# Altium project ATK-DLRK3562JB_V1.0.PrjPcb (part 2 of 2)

## Sheet 11_ATK-DLRK3562JB_RGMII_NET.SchDoc
size A4; Author: ALIENTEK; Revision: 0; SheetNumber: 11; SheetTotal: 11; Version: V1.0; SheetSize: A4
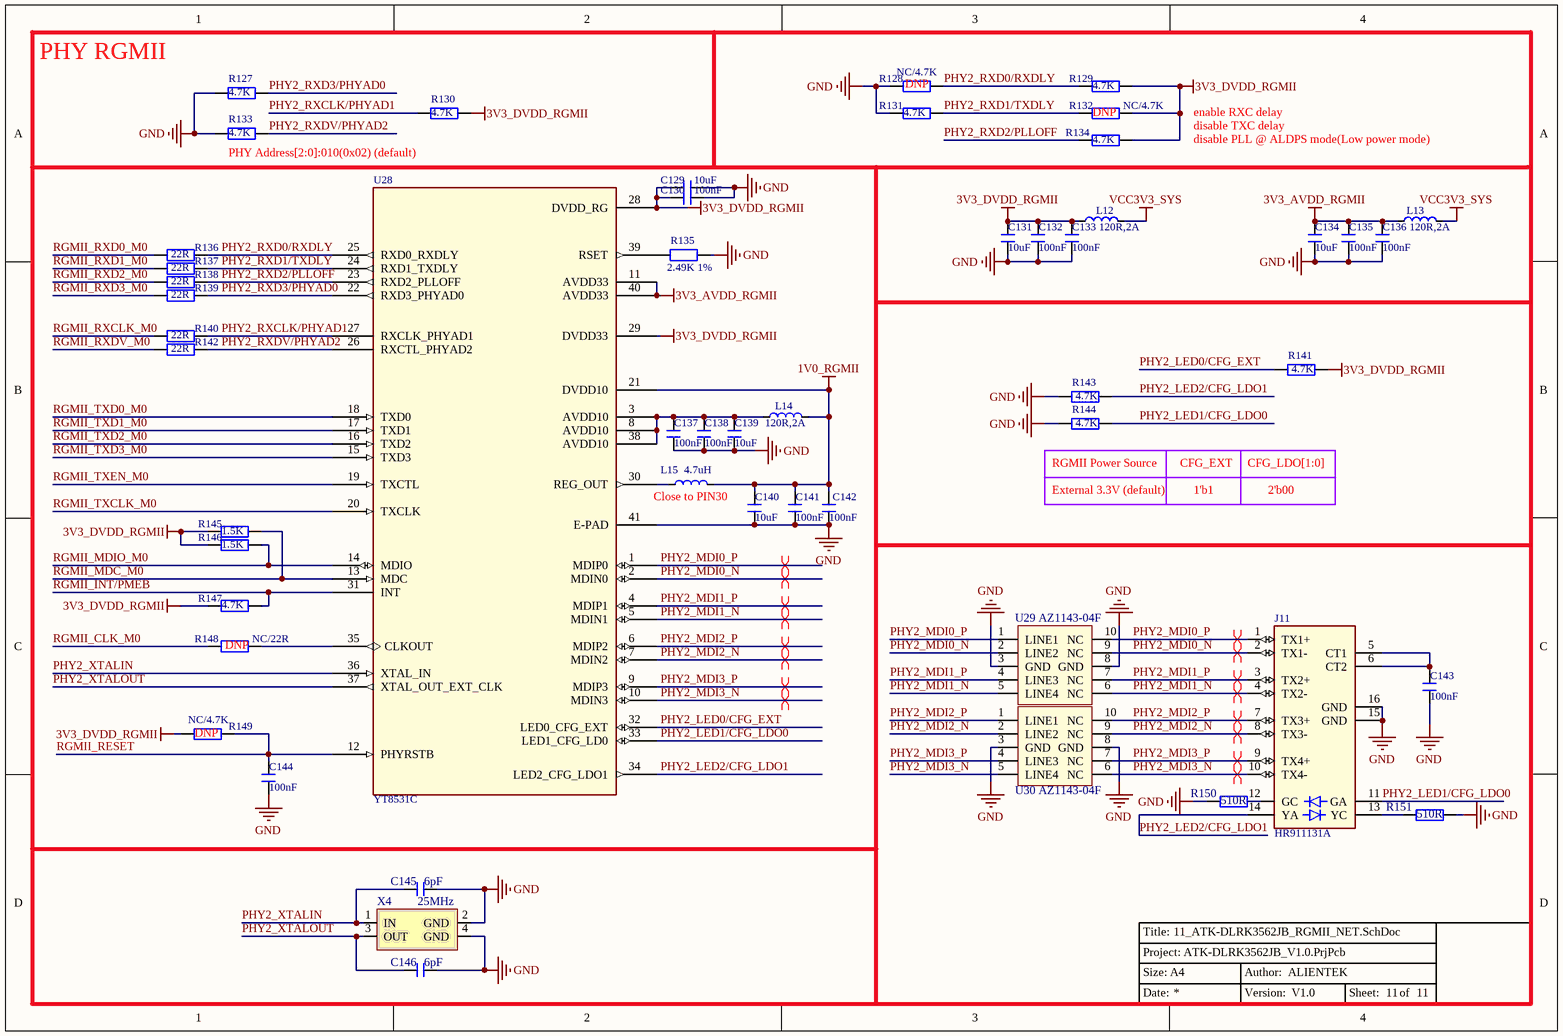
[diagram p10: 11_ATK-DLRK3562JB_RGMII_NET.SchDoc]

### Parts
C129  10uF  [C 0805]
C130  100nF  [C 0402]
C131  10uF  [C 0805]
C132  100nF  [C 0402]
C133  100nF  [C 0402]
C134  10uF  [C 0805]
C135  100nF  [C 0402]
C136  100nF  [C 0402]
C137  100nF  [C 0402]
C138  100nF  [C 0402]
C139  10uF  [C 0805]
C140  10uF  [C 0805]
C141  100nF  [C 0402]
C142  100nF  [C 0402]
C143  100nF  [C 0402]
C144  100nF  [C 0402]
C145  6pF  [C 0402]
C146  6pF  [C 0402]
J11  HR911131A  [HR911131A]
L12  120R,2A  [L 0603]
L13  120R,2A  [L 0603]
L14  120R,2A  [L 0603]
L15  4.7uH  [L_2520]
R127  4.7K  [R 0402]
R128  NC/4.7K  [R 0402]
R129  4.7K  [R 0402]
R130  4.7K  [R 0402]
R131  4.7K  [R 0402]
R132  NC/4.7K  [R 0402]
R133  4.7K  [R 0402]
R134  4.7K  [R 0402]
R135  2.49K 1%  [R 0402]
R136  22R  [R 0402]
R137  22R  [R 0402]
R138  22R  [R 0402]
R139  22R  [R 0402]
R140  22R  [R 0402]
R141  4.7K  [R 0402]
R142  22R  [R 0402]
R143  4.7K  [R 0402]
R144  4.7K  [R 0402]
R145  1.5K  [R 0402]
R146  1.5K  [R 0402]
R147  4.7K  [R 0402]
R148  NC/22R  [R 0402]
R149  NC/4.7K  [R 0402]
R150  510R  [R 0402]
R151  510R  [R 0402]
U28  YT8531C  [QFN40]
U29  AZ1143-04F  [DFN2510P10E]
U30  AZ1143-04F  [DFN2510P10E]
X4  25MHz  [XTAL-3225]

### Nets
1V0_RGMII: C140.2 C141.2 C142.2 L14.2 L15.2 U28.21(DVDD10)
3V3_AVDD_RGMII: C134.2 C135.2 C136.2 L13.1 U28.11(AVDD33) U28.40(AVDD33)
3V3_DVDD_RGMII: C129.2 C130.2 C131.2 C132.2 C133.2 L12.1 R129.2 R130.2 R132.2 R134.2 R141.2 R145.1 R146.1 R147.1 R149.2 U28.28(DVDD_RG) U28.29(DVDD33)
GND: C129.1 C130.1 C131.1 C132.1 C133.1 C134.1 C135.1 C136.1 C137.1 C138.1 C139.1 C140.1 C141.1 C142.1 C143.1 C144.1 C145.2 C146.2 J11.15(GND) J11.16(GND) R127.2 R128.1 R131.1 R133.2 R135.2 R143.1 R144.1 R150.1 R151.2 U28.41(E-PAD) U29.3(GND) U29.8(GND) U30.3(GND) U30.8(GND) X4.2(GND) X4.4(GND)
VCC3V3_SYS: L12.2 L13.2
PHY2_LED0/CFG_EXT: R141.1 U28.32(LED0_CFG_EXT)
PHY2_LED1/CFG_LDO0: J11.11(GA) R144.2 U28.33(LED1_CFG_LD0)
PHY2_LED2/CFG_LDO1: J11.14(YA) R143.2 U28.34(LED2_CFG_LDO1)
PHY2_MDI0_N: J11.2(TX1-) U28.2(MDIN0) U29.2(LINE2) U29.9(NC)
PHY2_MDI0_P: J11.1(TX1+) U28.1(MDIP0) U29.1(LINE1) U29.10(NC)
PHY2_MDI1_N: J11.4(TX2-) U28.5(MDIN1) U29.5(LINE4) U29.6(NC)
PHY2_MDI1_P: J11.3(TX2+) U28.4(MDIP1) U29.4(LINE3) U29.7(NC)
PHY2_MDI2_N: J11.8(TX3-) U28.7(MDIN2) U30.2(LINE2) U30.9(NC)
PHY2_MDI2_P: J11.7(TX3+) U28.6(MDIP2) U30.1(LINE1) U30.10(NC)
PHY2_MDI3_N: J11.10(TX4-) U28.10(MDIN3) U30.5(LINE4) U30.6(NC)
PHY2_MDI3_P: J11.9(TX4+) U28.9(MDIP3) U30.4(LINE3) U30.7(NC)
PHY2_RXCLK/PHYAD1: R130.1 R140.1 U28.27(RXCLK_PHYAD1)
PHY2_RXD0/RXDLY: R128.2 R129.1 R136.1 U28.25(RXD0_RXDLY)
PHY2_RXD1/TXDLY: R131.2 R132.1 R137.1 U28.24(RXD1_TXDLY)
PHY2_RXD2/PLLOFF: R134.1 R138.1 U28.23(RXD2_PLLOFF)
PHY2_RXD3/PHYAD0: R127.1 R139.1 U28.22(RXD3_PHYAD0)
PHY2_RXDV/PHYAD2: R133.1 R142.1 U28.26(RXCTL_PHYAD2)
PHY2_XTALIN: C145.1 U28.36(XTAL_IN) X4.1(IN)
PHY2_XTALOUT: C146.1 U28.37(XTAL_OUT_EXT_CLK) X4.3(OUT)
RGMII_CLK_M0: R148.1  [project net GPIO4_B7]
RGMII_INT/PMEB: R147.2 U28.31(INT)  [project net GPIO4_B1]
RGMII_MDC_M0: R145.2 U28.13(MDC)  [project net GPIO4_B2]
RGMII_MDIO_M0: R146.2 U28.14(MDIO)  [project net GPIO4_B3]
RGMII_RESET: C144.2 R149.1 U28.12(PHYRSTB)  [project net GPIO4_B0]
RGMII_RXCLK_M0: R140.2  [project net GPIO4_A1]
RGMII_RXD0_M0: R136.2  [project net GPIO4_A5]
RGMII_RXD1_M0: R137.2  [project net GPIO4_A6]
RGMII_RXD2_M0: R138.2  [project net GPIO3_D7]
RGMII_RXD3_M0: R139.2  [project net GPIO4_A0]
RGMII_RXDV_M0: R142.2  [project net GPIO4_A7]
RGMII_TXCLK_M0: U28.20(TXCLK)  [project net GPIO3_D6]
RGMII_TXD0_M0: U28.18(TXD0)  [project net GPIO4_A2]
RGMII_TXD1_M0: U28.17(TXD1)  [project net GPIO4_A3]
RGMII_TXD2_M0: U28.16(TXD2)  [project net GPIO3_D4]
RGMII_TXD3_M0: U28.15(TXD3)  [project net GPIO3_D5]
RGMII_TXEN_M0: U28.19(TXCTL)  [project net GPIO4_A4]
NetC137_2: C137.2 C138.2 C139.2 L14.1 U28.3(AVDD10) U28.8(AVDD10) U28.38(AVDD10)
NetC143_2: C143.2 J11.5(CT1) J11.6(CT2)
NetJ11_12: J11.12(GC) R150.2
NetJ11_13: J11.13(YC) R151.1
NetL15_1: L15.1 U28.30(REG_OUT)
NetR135_1: R135.1 U28.39(RSET)
NetR148_2: R148.2 U28.35(CLKOUT)

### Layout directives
differential pair: PHY2_MDI0_N, PHY2_MDI0_P, PHY2_MDI1_N, PHY2_MDI1_P, PHY2_MDI2_N, PHY2_MDI2_P, PHY2_MDI3_N, PHY2_MDI3_P

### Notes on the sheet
- PHY RGMII
- (near R128) DNP
- (near R132) DNP
- enable RXC delay
- (near R133) PHY Address[2:0]:010(0x02) (default)
- disable PLL @ ALDPS mode(Low power mode)
- disable TXC delay
- (near L15) Close to PIN30
- (near R144) RGMII Power Source
- External 3.3V (default)
- CFG_EXT
- 1'b1
- CFG_LDO[1:0]
- 2'b00
- (near R148) DNP
- (near R149) DNP

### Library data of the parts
C129-C144 = C: 无极性贴片电容; 版权归属: 源创客
C145 C146 = C: 无极性电容; BOM名称: 无极性贴片电容; 版权归属: 正点原子
J11 = HR911131A/C: 千兆以太网接口
L12-L15 = L: 小功率贴片电感磁珠; 版权归属: 源创客
R127-R149 = R: 贴片电阻; 版权归属: 源创客
R150 R151 = R: 贴片电阻; 版权归属: 正点原子
U28 = YT8531C: 千兆以太网
U29 U30 = AZ1143-04F: ESD保护二极管阵列
X4 = XTAL-4P: 4脚无源晶振; BOM名称: 4脚晶振; 版权归属: 正点原子; Parameter: 晶振

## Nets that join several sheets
GND: 02_ATK-DLRK3562JB_CORE_BOARD (72 pins), 03_ATK-DLRK3562JB_POWER_UART (52 pins), 04_ATK-DLRK3562JB_DEVICE1 (19 pins), 05_ATK-DLRK3562JB_DEVICE2 (45 pins), 06_ATK-DLRK3562JB_4G_HUB (40 pins), 07_ATK-DLRK3562JB_WIFI_TF_OTG_PINOUT (55 pins), 08_ATK-DLRK3562JB_PCIE_AUDIO (31 pins), 09_ATK-DLRK3562JB_LCD_CAMERA (45 pins), 10_ATK-DLRK3562JB_RMII_NET (24 pins), 11_ATK-DLRK3562JB_RGMII_NET (36 pins)
VCC3V3_SD: 02_ATK-DLRK3562JB_CORE_BOARD (U1.A9), 07_ATK-DLRK3562JB_WIFI_TF_OTG_PINOUT (L7.2)
VCC3V3_SYS: 02_ATK-DLRK3562JB_CORE_BOARD (8 pins), 03_ATK-DLRK3562JB_POWER_UART (11 pins), 04_ATK-DLRK3562JB_DEVICE1 (MOS2.1 R27.2), 05_ATK-DLRK3562JB_DEVICE2 (31 pins), 06_ATK-DLRK3562JB_4G_HUB (C97.2 L6.2), 07_ATK-DLRK3562JB_WIFI_TF_OTG_PINOUT (9 pins), 09_ATK-DLRK3562JB_LCD_CAMERA (8 pins), 10_ATK-DLRK3562JB_RMII_NET (L10.1 L11.1), 11_ATK-DLRK3562JB_RGMII_NET (L12.2 L13.2)
VCC5V0_SYS: 02_ATK-DLRK3562JB_CORE_BOARD (8 pins), 03_ATK-DLRK3562JB_POWER_UART (9 pins), 04_ATK-DLRK3562JB_DEVICE1 (R28.2), 05_ATK-DLRK3562JB_DEVICE2 (C46.1 C47.1 U13.3 U14.3), 07_ATK-DLRK3562JB_WIFI_TF_OTG_PINOUT (J9.2 J9.4), 08_ATK-DLRK3562JB_PCIE_AUDIO (C58.2 C59.2 R58.1 U16.1), 09_ATK-DLRK3562JB_LCD_CAMERA (7 pins)
VCC5V0_USB: 03_ATK-DLRK3562JB_POWER_UART (6 pins), 06_ATK-DLRK3562JB_4G_HUB (L5.2 U20.5 USB_HOST1.1 USB_HOST2.1), 07_ATK-DLRK3562JB_WIFI_TF_OTG_PINOUT (L9.1)
VCC12V_DCIN: 03_ATK-DLRK3562JB_POWER_UART (16 pins), 04_ATK-DLRK3562JB_DEVICE1 (C31.1 C32.1 J4.2), 08_ATK-DLRK3562JB_PCIE_AUDIO (7 pins)
VCC_1V8: 02_ATK-DLRK3562JB_CORE_BOARD (U1.A111), 04_ATK-DLRK3562JB_DEVICE1 (R30.1 R31.1 VR.3), 09_ATK-DLRK3562JB_LCD_CAMERA (13 pins)
VCCIO_SD: 02_ATK-DLRK3562JB_CORE_BOARD (U1.A112), 07_ATK-DLRK3562JB_WIFI_TF_OTG_PINOUT (R96.1 R100.1)
CAM0_PWDN: 02_ATK-DLRK3562JB_CORE_BOARD (U1.B57), 07_ATK-DLRK3562JB_WIFI_TF_OTG_PINOUT (J9.13), 09_ATK-DLRK3562JB_LCD_CAMERA (R63.1)
CAM0_RESET: 02_ATK-DLRK3562JB_CORE_BOARD (U1.B58), 07_ATK-DLRK3562JB_WIFI_TF_OTG_PINOUT (J9.15), 09_ATK-DLRK3562JB_LCD_CAMERA (R62.1)
CAM1_PWDN: 02_ATK-DLRK3562JB_CORE_BOARD (U1.B56), 07_ATK-DLRK3562JB_WIFI_TF_OTG_PINOUT (J9.11), 09_ATK-DLRK3562JB_LCD_CAMERA (R78.1)
CAM1_RESET: 02_ATK-DLRK3562JB_CORE_BOARD (U1.B59), 07_ATK-DLRK3562JB_WIFI_TF_OTG_PINOUT (J9.19), 09_ATK-DLRK3562JB_LCD_CAMERA (R73.1)
CAN0_RX: 02_ATK-DLRK3562JB_CORE_BOARD (U1.A86), 05_ATK-DLRK3562JB_DEVICE2 (U13.4)
CAN0_TX: 02_ATK-DLRK3562JB_CORE_BOARD (U1.A85), 05_ATK-DLRK3562JB_DEVICE2 (U13.1)
CAN1_RX: 02_ATK-DLRK3562JB_CORE_BOARD (U1.A84), 05_ATK-DLRK3562JB_DEVICE2 (U14.4)
CAN1_TX: 02_ATK-DLRK3562JB_CORE_BOARD (U1.A83), 05_ATK-DLRK3562JB_DEVICE2 (U14.1)
DSI_RESET: 02_ATK-DLRK3562JB_CORE_BOARD (U1.B81), 07_ATK-DLRK3562JB_WIFI_TF_OTG_PINOUT (J9.7), 09_ATK-DLRK3562JB_LCD_CAMERA (R70.1)
GPIO0_A0: 02_ATK-DLRK3562JB_CORE_BOARD (U1.A54), 07_ATK-DLRK3562JB_WIFI_TF_OTG_PINOUT (J9.3), 09_ATK-DLRK3562JB_LCD_CAMERA (LVDS.28 MIPI_DSI.21)
GPIO0_A4: 02_ATK-DLRK3562JB_CORE_BOARD (U1.A68), 07_ATK-DLRK3562JB_WIFI_TF_OTG_PINOUT (R103.2)
GPIO0_A5: 02_ATK-DLRK3562JB_CORE_BOARD (U1.A92), 08_ATK-DLRK3562JB_PCIE_AUDIO (J8.B17 R110.2)
GPIO0_A6: 02_ATK-DLRK3562JB_CORE_BOARD (U1.A91), 08_ATK-DLRK3562JB_PCIE_AUDIO (J8.B12)
GPIO0_B0: 02_ATK-DLRK3562JB_CORE_BOARD (U1.A55), 07_ATK-DLRK3562JB_WIFI_TF_OTG_PINOUT (J9.5), 09_ATK-DLRK3562JB_LCD_CAMERA (LVDS.36 MIPI_DSI.24)
GPIO0_B1: 02_ATK-DLRK3562JB_CORE_BOARD (U1.A102), 07_ATK-DLRK3562JB_WIFI_TF_OTG_PINOUT (J9.10)
GPIO0_B2: 02_ATK-DLRK3562JB_CORE_BOARD (U1.A101), 07_ATK-DLRK3562JB_WIFI_TF_OTG_PINOUT (J9.12)
GPIO0_B3: 02_ATK-DLRK3562JB_CORE_BOARD (U1.A100), 05_ATK-DLRK3562JB_DEVICE2 (R35.1 U8.6 U9.6), 07_ATK-DLRK3562JB_WIFI_TF_OTG_PINOUT (J9.16 U25.6)
GPIO0_B4: 02_ATK-DLRK3562JB_CORE_BOARD (U1.A99), 05_ATK-DLRK3562JB_DEVICE2 (R36.1 U8.5 U9.5), 07_ATK-DLRK3562JB_WIFI_TF_OTG_PINOUT (J9.18 U25.7)
GPIO0_B5: 02_ATK-DLRK3562JB_CORE_BOARD (U1.A90), 08_ATK-DLRK3562JB_PCIE_AUDIO (J8.A11)
GPIO0_B6: 02_ATK-DLRK3562JB_CORE_BOARD (U1.A89), 08_ATK-DLRK3562JB_PCIE_AUDIO (J8.B11 R34.2)
GPIO0_B7: 02_ATK-DLRK3562JB_CORE_BOARD (U1.A88), 08_ATK-DLRK3562JB_PCIE_AUDIO (R83.1 R88.2)
GPIO0_C2: 02_ATK-DLRK3562JB_CORE_BOARD (U1.A95), 05_ATK-DLRK3562JB_DEVICE2 (U10.1), 07_ATK-DLRK3562JB_WIFI_TF_OTG_PINOUT (J9.26)
GPIO0_C3: 02_ATK-DLRK3562JB_CORE_BOARD (U1.A94), 05_ATK-DLRK3562JB_DEVICE2 (U10.6), 07_ATK-DLRK3562JB_WIFI_TF_OTG_PINOUT (J9.22)
GPIO0_C4: 02_ATK-DLRK3562JB_CORE_BOARD (U1.A96), 05_ATK-DLRK3562JB_DEVICE2 (U10.5), 07_ATK-DLRK3562JB_WIFI_TF_OTG_PINOUT (J9.24)
GPIO0_C5: 02_ATK-DLRK3562JB_CORE_BOARD (U1.A97), 05_ATK-DLRK3562JB_DEVICE2 (U10.2), 07_ATK-DLRK3562JB_WIFI_TF_OTG_PINOUT (J9.28)
GPIO0_D0: 02_ATK-DLRK3562JB_CORE_BOARD (U1.A53), 03_ATK-DLRK3562JB_POWER_UART (J3.3)
GPIO0_D1: 02_ATK-DLRK3562JB_CORE_BOARD (U1.A52), 03_ATK-DLRK3562JB_POWER_UART (J3.1)
GPIO1_B3: 02_ATK-DLRK3562JB_CORE_BOARD (U1.A70), 07_ATK-DLRK3562JB_WIFI_TF_OTG_PINOUT (R100.2 R101.2)
GPIO1_B4: 02_ATK-DLRK3562JB_CORE_BOARD (U1.A69), 07_ATK-DLRK3562JB_WIFI_TF_OTG_PINOUT (R102.2)
GPIO1_B5: 02_ATK-DLRK3562JB_CORE_BOARD (U1.A74), 07_ATK-DLRK3562JB_WIFI_TF_OTG_PINOUT (R95.2)
GPIO1_B6: 02_ATK-DLRK3562JB_CORE_BOARD (U1.A73), 07_ATK-DLRK3562JB_WIFI_TF_OTG_PINOUT (R97.2)
GPIO1_B7: 02_ATK-DLRK3562JB_CORE_BOARD (U1.A72), 07_ATK-DLRK3562JB_WIFI_TF_OTG_PINOUT (R96.2 R98.2)
GPIO1_C0: 02_ATK-DLRK3562JB_CORE_BOARD (U1.A71), 07_ATK-DLRK3562JB_WIFI_TF_OTG_PINOUT (R99.2)
GPIO1_C1: 02_ATK-DLRK3562JB_CORE_BOARD (U1.A77), 07_ATK-DLRK3562JB_WIFI_TF_OTG_PINOUT (J9.35)
GPIO1_C2: 02_ATK-DLRK3562JB_CORE_BOARD (U1.A78), 07_ATK-DLRK3562JB_WIFI_TF_OTG_PINOUT (J9.33)
GPIO1_C3: 02_ATK-DLRK3562JB_CORE_BOARD (U1.A76), 07_ATK-DLRK3562JB_WIFI_TF_OTG_PINOUT (J9.37)
GPIO1_C4: 02_ATK-DLRK3562JB_CORE_BOARD (U1.A79), 07_ATK-DLRK3562JB_WIFI_TF_OTG_PINOUT (J9.31)
GPIO1_C5: 02_ATK-DLRK3562JB_CORE_BOARD (U1.A80), 07_ATK-DLRK3562JB_WIFI_TF_OTG_PINOUT (J9.29)
GPIO1_C6: 02_ATK-DLRK3562JB_CORE_BOARD (U1.A81), 07_ATK-DLRK3562JB_WIFI_TF_OTG_PINOUT (J9.27)
GPIO1_C7: 02_ATK-DLRK3562JB_CORE_BOARD (U1.A49), 10_ATK-DLRK3562JB_RMII_NET (R120.2 U26.22)
GPIO1_D0: 02_ATK-DLRK3562JB_CORE_BOARD (U1.A50), 10_ATK-DLRK3562JB_RMII_NET (R119.2 U26.23)
GPIO1_D1: 02_ATK-DLRK3562JB_CORE_BOARD (U1.A40), 10_ATK-DLRK3562JB_RMII_NET (U26.16)
GPIO1_D2: 02_ATK-DLRK3562JB_CORE_BOARD (U1.A41), 10_ATK-DLRK3562JB_RMII_NET (U26.17)
GPIO1_D3: 02_ATK-DLRK3562JB_CORE_BOARD (U1.A42), 10_ATK-DLRK3562JB_RMII_NET (U26.20)
GPIO1_D4: 02_ATK-DLRK3562JB_CORE_BOARD (U1.A43), 10_ATK-DLRK3562JB_RMII_NET (U26.9)
GPIO1_D5: 02_ATK-DLRK3562JB_CORE_BOARD (U1.A47), 10_ATK-DLRK3562JB_RMII_NET (R118.1)
GPIO1_D6: 02_ATK-DLRK3562JB_CORE_BOARD (U1.A46), 10_ATK-DLRK3562JB_RMII_NET (U26.26)
GPIO1_D7: 02_ATK-DLRK3562JB_CORE_BOARD (U1.A44), 10_ATK-DLRK3562JB_RMII_NET (R109.2 U26.10)
GPIO2_A0: 02_ATK-DLRK3562JB_CORE_BOARD (U1.A45), 10_ATK-DLRK3562JB_RMII_NET (U26.28)
GPIO2_A1: 02_ATK-DLRK3562JB_CORE_BOARD (U1.A48), 10_ATK-DLRK3562JB_RMII_NET (C122.2 R123.2 U26.21)
GPIO3_A0: 02_ATK-DLRK3562JB_CORE_BOARD (U1.B80), 07_ATK-DLRK3562JB_WIFI_TF_OTG_PINOUT (R106.2 U24.4)
GPIO3_A1: 02_ATK-DLRK3562JB_CORE_BOARD (U1.B79), 07_ATK-DLRK3562JB_WIFI_TF_OTG_PINOUT (R18.2 U25.5)
GPIO3_A7: 02_ATK-DLRK3562JB_CORE_BOARD (U1.B112), 07_ATK-DLRK3562JB_WIFI_TF_OTG_PINOUT (J9.8), 08_ATK-DLRK3562JB_PCIE_AUDIO (R54.1 R55.2)
GPIO3_B2: 02_ATK-DLRK3562JB_CORE_BOARD (U1.B72), 05_ATK-DLRK3562JB_DEVICE2 (R114.1 U12.4)
GPIO3_B3: 02_ATK-DLRK3562JB_CORE_BOARD (U1.B71), 05_ATK-DLRK3562JB_DEVICE2 (R46.1 U12.1)
GPIO3_B6: 02_ATK-DLRK3562JB_CORE_BOARD (U1.B51), 09_ATK-DLRK3562JB_LCD_CAMERA (Q5.3 R66.1)
GPIO3_B7: 02_ATK-DLRK3562JB_CORE_BOARD (U1.B52), 09_ATK-DLRK3562JB_LCD_CAMERA (Q6.3 R68.1)
GPIO3_C2: 02_ATK-DLRK3562JB_CORE_BOARD (U1.B53), 09_ATK-DLRK3562JB_LCD_CAMERA (Q7.3 R74.1)
GPIO3_C3: 02_ATK-DLRK3562JB_CORE_BOARD (U1.B54), 09_ATK-DLRK3562JB_LCD_CAMERA (Q8.3 R79.1)
GPIO3_C4: 02_ATK-DLRK3562JB_CORE_BOARD (U1.B74), 05_ATK-DLRK3562JB_DEVICE2 (R111.1 U11.4)
GPIO3_C5: 02_ATK-DLRK3562JB_CORE_BOARD (U1.B47), 07_ATK-DLRK3562JB_WIFI_TF_OTG_PINOUT (J9.23), 09_ATK-DLRK3562JB_LCD_CAMERA (LVDS.27 MIPI_DSI.20)
GPIO3_C6: 02_ATK-DLRK3562JB_CORE_BOARD (U1.B45), 04_ATK-DLRK3562JB_DEVICE1 (MOS2.2 R25.1 R27.1), 07_ATK-DLRK3562JB_WIFI_TF_OTG_PINOUT (J9.21)
GPIO3_C7: 02_ATK-DLRK3562JB_CORE_BOARD (U1.B73), 05_ATK-DLRK3562JB_DEVICE2 (R45.1 U11.1)
GPIO3_D0: 02_ATK-DLRK3562JB_CORE_BOARD (U1.B76), 05_ATK-DLRK3562JB_DEVICE2 (U15.11)
GPIO3_D1: 02_ATK-DLRK3562JB_CORE_BOARD (U1.B75), 05_ATK-DLRK3562JB_DEVICE2 (U15.12)
GPIO3_D2: 02_ATK-DLRK3562JB_CORE_BOARD (U1.B49), 05_ATK-DLRK3562JB_DEVICE2 (R82.1), 09_ATK-DLRK3562JB_LCD_CAMERA (LVDS.34 MIPI_DSI.23)
GPIO3_D3: 02_ATK-DLRK3562JB_CORE_BOARD (U1.B50), 05_ATK-DLRK3562JB_DEVICE2 (R152.1), 09_ATK-DLRK3562JB_LCD_CAMERA (LVDS.33 MIPI_DSI.22)
GPIO3_D4: 02_ATK-DLRK3562JB_CORE_BOARD (U1.B93), 11_ATK-DLRK3562JB_RGMII_NET (U28.16)
GPIO3_D5: 02_ATK-DLRK3562JB_CORE_BOARD (U1.B92), 11_ATK-DLRK3562JB_RGMII_NET (U28.15)
GPIO3_D6: 02_ATK-DLRK3562JB_CORE_BOARD (U1.B90), 11_ATK-DLRK3562JB_RGMII_NET (U28.20)
GPIO3_D7: 02_ATK-DLRK3562JB_CORE_BOARD (U1.B86), 11_ATK-DLRK3562JB_RGMII_NET (R138.2)
GPIO4_A0: 02_ATK-DLRK3562JB_CORE_BOARD (U1.B85), 11_ATK-DLRK3562JB_RGMII_NET (R139.2)
GPIO4_A1: 02_ATK-DLRK3562JB_CORE_BOARD (U1.B83), 11_ATK-DLRK3562JB_RGMII_NET (R140.2)
GPIO4_A2: 02_ATK-DLRK3562JB_CORE_BOARD (U1.B95), 11_ATK-DLRK3562JB_RGMII_NET (U28.18)
GPIO4_A3: 02_ATK-DLRK3562JB_CORE_BOARD (U1.B94), 11_ATK-DLRK3562JB_RGMII_NET (U28.17)
GPIO4_A4: 02_ATK-DLRK3562JB_CORE_BOARD (U1.B91), 11_ATK-DLRK3562JB_RGMII_NET (U28.19)
GPIO4_A5: 02_ATK-DLRK3562JB_CORE_BOARD (U1.B88), 11_ATK-DLRK3562JB_RGMII_NET (R136.2)
GPIO4_A6: 02_ATK-DLRK3562JB_CORE_BOARD (U1.B87), 11_ATK-DLRK3562JB_RGMII_NET (R137.2)
GPIO4_A7: 02_ATK-DLRK3562JB_CORE_BOARD (U1.B84), 11_ATK-DLRK3562JB_RGMII_NET (R142.2)
GPIO4_B0: 02_ATK-DLRK3562JB_CORE_BOARD (U1.B40), 11_ATK-DLRK3562JB_RGMII_NET (C144.2 R149.1 U28.12)
GPIO4_B1: 02_ATK-DLRK3562JB_CORE_BOARD (U1.B41), 11_ATK-DLRK3562JB_RGMII_NET (R147.2 U28.31)
GPIO4_B2: 02_ATK-DLRK3562JB_CORE_BOARD (U1.B42), 11_ATK-DLRK3562JB_RGMII_NET (R145.2 U28.13)
GPIO4_B3: 02_ATK-DLRK3562JB_CORE_BOARD (U1.B43), 11_ATK-DLRK3562JB_RGMII_NET (R146.2 U28.14)
GPIO4_B4: 02_ATK-DLRK3562JB_CORE_BOARD (U1.B78), 05_ATK-DLRK3562JB_DEVICE2 (U31.11), 07_ATK-DLRK3562JB_WIFI_TF_OTG_PINOUT (J9.36)
GPIO4_B5: 02_ATK-DLRK3562JB_CORE_BOARD (U1.B77), 05_ATK-DLRK3562JB_DEVICE2 (U31.12), 07_ATK-DLRK3562JB_WIFI_TF_OTG_PINOUT (J9.38)
GPIO4_B6: 02_ATK-DLRK3562JB_CORE_BOARD (U1.B46), 03_ATK-DLRK3562JB_POWER_UART (R6.2), 07_ATK-DLRK3562JB_WIFI_TF_OTG_PINOUT (J9.40)
GPIO4_B7: 02_ATK-DLRK3562JB_CORE_BOARD (U1.B39), 11_ATK-DLRK3562JB_RGMII_NET (R148.1)
HP_SNS: 02_ATK-DLRK3562JB_CORE_BOARD (U1.B114), 08_ATK-DLRK3562JB_PCIE_AUDIO (R51.2)
HPL_OUT: 02_ATK-DLRK3562JB_CORE_BOARD (U1.B115), 08_ATK-DLRK3562JB_PCIE_AUDIO (C56.1)
HPR_OUT: 02_ATK-DLRK3562JB_CORE_BOARD (U1.B113), 08_ATK-DLRK3562JB_PCIE_AUDIO (C55.1)
HUB_D1_N: 06_ATK-DLRK3562JB_4G_HUB (U19.7), 07_ATK-DLRK3562JB_WIFI_TF_OTG_PINOUT (U23.12)
HUB_D1_P: 06_ATK-DLRK3562JB_4G_HUB (U19.8), 07_ATK-DLRK3562JB_WIFI_TF_OTG_PINOUT (U23.13)
MIC1_INN: 02_ATK-DLRK3562JB_CORE_BOARD (U1.B116), 08_ATK-DLRK3562JB_PCIE_AUDIO (C62.2 MIC.2 R59.2)
MIC1_INP: 02_ATK-DLRK3562JB_CORE_BOARD (U1.B117), 08_ATK-DLRK3562JB_PCIE_AUDIO (C62.1 MIC.1 R57.2)
MIPI_CSI_RX0_CLK0_N: 02_ATK-DLRK3562JB_CORE_BOARD (U1.B15), 09_ATK-DLRK3562JB_LCD_CAMERA (J6.10)
MIPI_CSI_RX0_CLK0_P: 02_ATK-DLRK3562JB_CORE_BOARD (U1.B16), 09_ATK-DLRK3562JB_LCD_CAMERA (J6.8)
MIPI_CSI_RX0_D0_N: 02_ATK-DLRK3562JB_CORE_BOARD (U1.B3), 09_ATK-DLRK3562JB_LCD_CAMERA (J6.11)
MIPI_CSI_RX0_D0_P: 02_ATK-DLRK3562JB_CORE_BOARD (U1.B4), 09_ATK-DLRK3562JB_LCD_CAMERA (J6.9)
MIPI_CSI_RX0_D1_N: 02_ATK-DLRK3562JB_CORE_BOARD (U1.B6), 09_ATK-DLRK3562JB_LCD_CAMERA (J6.16)
MIPI_CSI_RX0_D1_P: 02_ATK-DLRK3562JB_CORE_BOARD (U1.B7), 09_ATK-DLRK3562JB_LCD_CAMERA (J6.14)
MIPI_CSI_RX0_D2_N: 02_ATK-DLRK3562JB_CORE_BOARD (U1.B9), 09_ATK-DLRK3562JB_LCD_CAMERA (J6.5)
MIPI_CSI_RX0_D2_P: 02_ATK-DLRK3562JB_CORE_BOARD (U1.B10), 09_ATK-DLRK3562JB_LCD_CAMERA (J6.3)
MIPI_CSI_RX0_D3_N: 02_ATK-DLRK3562JB_CORE_BOARD (U1.B12), 09_ATK-DLRK3562JB_LCD_CAMERA (J6.4)
MIPI_CSI_RX0_D3_P: 02_ATK-DLRK3562JB_CORE_BOARD (U1.B13), 09_ATK-DLRK3562JB_LCD_CAMERA (J6.2)
MIPI_CSI_RX1_CLK0_N: 02_ATK-DLRK3562JB_CORE_BOARD (U1.B33), 09_ATK-DLRK3562JB_LCD_CAMERA (J7.10)
MIPI_CSI_RX1_CLK0_P: 02_ATK-DLRK3562JB_CORE_BOARD (U1.B34), 09_ATK-DLRK3562JB_LCD_CAMERA (J7.8)
MIPI_CSI_RX1_D0_N: 02_ATK-DLRK3562JB_CORE_BOARD (U1.B21), 09_ATK-DLRK3562JB_LCD_CAMERA (J7.11)
MIPI_CSI_RX1_D0_P: 02_ATK-DLRK3562JB_CORE_BOARD (U1.B22), 09_ATK-DLRK3562JB_LCD_CAMERA (J7.9)
MIPI_CSI_RX1_D1_N: 02_ATK-DLRK3562JB_CORE_BOARD (U1.B24), 09_ATK-DLRK3562JB_LCD_CAMERA (J7.16)
MIPI_CSI_RX1_D1_P: 02_ATK-DLRK3562JB_CORE_BOARD (U1.B25), 09_ATK-DLRK3562JB_LCD_CAMERA (J7.14)
MIPI_CSI_RX1_D2_N: 02_ATK-DLRK3562JB_CORE_BOARD (U1.B27), 09_ATK-DLRK3562JB_LCD_CAMERA (J7.5)
MIPI_CSI_RX1_D2_P: 02_ATK-DLRK3562JB_CORE_BOARD (U1.B28), 09_ATK-DLRK3562JB_LCD_CAMERA (J7.3)
MIPI_CSI_RX1_D3_N: 02_ATK-DLRK3562JB_CORE_BOARD (U1.B30), 09_ATK-DLRK3562JB_LCD_CAMERA (J7.4)
MIPI_CSI_RX1_D3_P: 02_ATK-DLRK3562JB_CORE_BOARD (U1.B31), 09_ATK-DLRK3562JB_LCD_CAMERA (J7.2)
MIPI_DSI_TX_CLK_N/LVDS_TX_CLK_N: 02_ATK-DLRK3562JB_CORE_BOARD (U1.B97), 09_ATK-DLRK3562JB_LCD_CAMERA (LVDS.17 MIPI_DSI.13)
MIPI_DSI_TX_CLK_P/LVDS_TX_CLK_P: 02_ATK-DLRK3562JB_CORE_BOARD (U1.B98), 09_ATK-DLRK3562JB_LCD_CAMERA (LVDS.18 MIPI_DSI.14)
MIPI_DSI_TX_D0_N/LVDS_TX_D0_N: 02_ATK-DLRK3562JB_CORE_BOARD (U1.B109), 09_ATK-DLRK3562JB_LCD_CAMERA (LVDS.8 MIPI_DSI.10)
MIPI_DSI_TX_D0_P/LVDS_TX_D0_P: 02_ATK-DLRK3562JB_CORE_BOARD (U1.B110), 09_ATK-DLRK3562JB_LCD_CAMERA (LVDS.9 MIPI_DSI.11)
MIPI_DSI_TX_D1_N/LVDS_TX_D1_N: 02_ATK-DLRK3562JB_CORE_BOARD (U1.B106), 09_ATK-DLRK3562JB_LCD_CAMERA (LVDS.11 MIPI_DSI.16)
MIPI_DSI_TX_D1_P/LVDS_TX_D1_P: 02_ATK-DLRK3562JB_CORE_BOARD (U1.B107), 09_ATK-DLRK3562JB_LCD_CAMERA (LVDS.12 MIPI_DSI.17)
MIPI_DSI_TX_D2_N/LVDS_TX_D2_N: 02_ATK-DLRK3562JB_CORE_BOARD (U1.B103), 09_ATK-DLRK3562JB_LCD_CAMERA (LVDS.14 MIPI_DSI.7)
MIPI_DSI_TX_D2_P/LVDS_TX_D2_P: 02_ATK-DLRK3562JB_CORE_BOARD (U1.B104), 09_ATK-DLRK3562JB_LCD_CAMERA (LVDS.15 MIPI_DSI.8)
MIPI_DSI_TX_D3_N/LVDS_TX_D3_N: 02_ATK-DLRK3562JB_CORE_BOARD (U1.B100), 09_ATK-DLRK3562JB_LCD_CAMERA (LVDS.20 MIPI_DSI.4)
MIPI_DSI_TX_D3_P/LVDS_TX_D3_P: 02_ATK-DLRK3562JB_CORE_BOARD (U1.B101), 09_ATK-DLRK3562JB_LCD_CAMERA (LVDS.21 MIPI_DSI.5)
PCIE20_REFCLKN: 02_ATK-DLRK3562JB_CORE_BOARD (U1.A35), 08_ATK-DLRK3562JB_PCIE_AUDIO (J8.A14)
PCIE20_REFCLKP: 02_ATK-DLRK3562JB_CORE_BOARD (U1.A34), 08_ATK-DLRK3562JB_PCIE_AUDIO (J8.A13)
PMIC_32KOUT: 02_ATK-DLRK3562JB_CORE_BOARD (U1.A20), 07_ATK-DLRK3562JB_WIFI_TF_OTG_PINOUT (J9.32)
PMIC_EXT_EN: 02_ATK-DLRK3562JB_CORE_BOARD (U1.A19), 03_ATK-DLRK3562JB_POWER_UART (R8.2 R19.2)
PMIC_PWRON: 02_ATK-DLRK3562JB_CORE_BOARD (U1.A21), 04_ATK-DLRK3562JB_DEVICE1 (C34.1 PWRON.1)
RESET: 02_ATK-DLRK3562JB_CORE_BOARD (U1.A18), 04_ATK-DLRK3562JB_DEVICE1 (C33.1 RESET.1)
SARADC0_BOOT: 02_ATK-DLRK3562JB_CORE_BOARD (U1.A62), 04_ATK-DLRK3562JB_DEVICE1 (C35.1 MASKROM.1 R30.2 R32.1)
SARADC0_IN1_KEY/RECOVERY: 02_ATK-DLRK3562JB_CORE_BOARD (U1.A57), 04_ATK-DLRK3562JB_DEVICE1 (R23.2 R24.2)
SARADC0_IN2_HW_ID: 02_ATK-DLRK3562JB_CORE_BOARD (U1.A58), 04_ATK-DLRK3562JB_DEVICE1 (R31.2 R33.1)
SARADC0_IN3_LCD_ID: 02_ATK-DLRK3562JB_CORE_BOARD (U1.A59), 09_ATK-DLRK3562JB_LCD_CAMERA (MIPI_DSI.19 R61.1)
SARADC0_IN4: 02_ATK-DLRK3562JB_CORE_BOARD (U1.A63), 04_ATK-DLRK3562JB_DEVICE1 (J12.1)
SARADC0_IN5: 02_ATK-DLRK3562JB_CORE_BOARD (U1.A64), 04_ATK-DLRK3562JB_DEVICE1 (J12.4)
SARADC0_IN6: 02_ATK-DLRK3562JB_CORE_BOARD (U1.A65), 04_ATK-DLRK3562JB_DEVICE1 (J12.3)
SARADC0_IN7: 02_ATK-DLRK3562JB_CORE_BOARD (U1.A66), 04_ATK-DLRK3562JB_DEVICE1 (J12.6)
SARADC1_IN0: 02_ATK-DLRK3562JB_CORE_BOARD (U1.B62), 04_ATK-DLRK3562JB_DEVICE1 (J12.7)
SARADC1_IN1: 02_ATK-DLRK3562JB_CORE_BOARD (U1.B63), 04_ATK-DLRK3562JB_DEVICE1 (J12.8)
SARADC1_IN2: 02_ATK-DLRK3562JB_CORE_BOARD (U1.B64), 04_ATK-DLRK3562JB_DEVICE1 (J12.9)
SARADC1_IN3: 02_ATK-DLRK3562JB_CORE_BOARD (U1.B65), 04_ATK-DLRK3562JB_DEVICE1 (J12.10)
SARADC1_IN4: 02_ATK-DLRK3562JB_CORE_BOARD (U1.B66), 04_ATK-DLRK3562JB_DEVICE1 (J12.11)
SARADC1_IN5: 02_ATK-DLRK3562JB_CORE_BOARD (U1.B67), 04_ATK-DLRK3562JB_DEVICE1 (J12.12)
SARADC1_IN6: 02_ATK-DLRK3562JB_CORE_BOARD (U1.B68), 04_ATK-DLRK3562JB_DEVICE1 (J12.13)
SARADC1_IN7: 02_ATK-DLRK3562JB_CORE_BOARD (U1.B69), 04_ATK-DLRK3562JB_DEVICE1 (J12.14)
SPKN_OUT: 02_ATK-DLRK3562JB_CORE_BOARD (U1.B118), 08_ATK-DLRK3562JB_PCIE_AUDIO (L16.1)
SPKP_OUT: 02_ATK-DLRK3562JB_CORE_BOARD (U1.B119), 08_ATK-DLRK3562JB_PCIE_AUDIO (L17.1)
USB20_HOST1_DM: 02_ATK-DLRK3562JB_CORE_BOARD (U1.A29), 06_ATK-DLRK3562JB_4G_HUB (U19.10)
USB20_HOST1_DP: 02_ATK-DLRK3562JB_CORE_BOARD (U1.A28), 06_ATK-DLRK3562JB_4G_HUB (U19.11)
USB30_OTG0_DM: 02_ATK-DLRK3562JB_CORE_BOARD (U1.A26), 07_ATK-DLRK3562JB_WIFI_TF_OTG_PINOUT (USB_OTG.5 USB_OTG.7 VD7.1)
USB30_OTG0_DP: 02_ATK-DLRK3562JB_CORE_BOARD (U1.A25), 07_ATK-DLRK3562JB_WIFI_TF_OTG_PINOUT (USB_OTG.6 USB_OTG.8 VD6.1)
USB30_OTG0_SSRXN/PCIE20_RXDN: 02_ATK-DLRK3562JB_CORE_BOARD (U1.A38), 08_ATK-DLRK3562JB_PCIE_AUDIO (J8.A17)
USB30_OTG0_SSRXP/PCIE20_RXDP: 02_ATK-DLRK3562JB_CORE_BOARD (U1.A37), 08_ATK-DLRK3562JB_PCIE_AUDIO (J8.A16)
USB30_OTG0_SSTXN/PCIE20_TXDN: 02_ATK-DLRK3562JB_CORE_BOARD (U1.A32), 08_ATK-DLRK3562JB_PCIE_AUDIO (C77.1)
USB30_OTG0_SSTXP/PCIE20_TXDP: 02_ATK-DLRK3562JB_CORE_BOARD (U1.A31), 08_ATK-DLRK3562JB_PCIE_AUDIO (C76.1)
USB30_OTG0_VBUSDET: 02_ATK-DLRK3562JB_CORE_BOARD (U1.A23), 07_ATK-DLRK3562JB_WIFI_TF_OTG_PINOUT (R107.1 R108.1)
